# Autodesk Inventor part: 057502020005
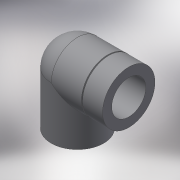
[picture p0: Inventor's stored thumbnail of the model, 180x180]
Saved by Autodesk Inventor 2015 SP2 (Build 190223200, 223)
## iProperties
Created: 2017-10
Part Number: 057502020005
Material: Generic
Description: ELBOW 90° THR-CEM REINF. R 20-1/2"
Document SubType Name: Modeling
Designer: KIM
Density: 1 g/cm^3
Appearance: Default
Author: KIM
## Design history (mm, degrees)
derived "057502.ipt"
feature "Solid1::057502.ipt"
tag "TaggingFeature1"
body "Solid1"
other parameters: "d0" = 28.5, "d1" = 25, "d3" = 27, "d4" = 25, "d6" = 90 deg, "d7" = 18.631, "d8" = 17, "d9" = 0, "d11" = 16, "d12" = 0, "d14" = 14.9048, "d16" = 9.3155, "d17" = 0, "d18" = 0, "d19" = 25, "d20" = 11.4, "d21" = 0.5, "d22" = 0.5, "G_" = 18.631, "E_" = 25, "l_" = 16, "lt_" = 17, "Z_" = 11, "H_" = 41
